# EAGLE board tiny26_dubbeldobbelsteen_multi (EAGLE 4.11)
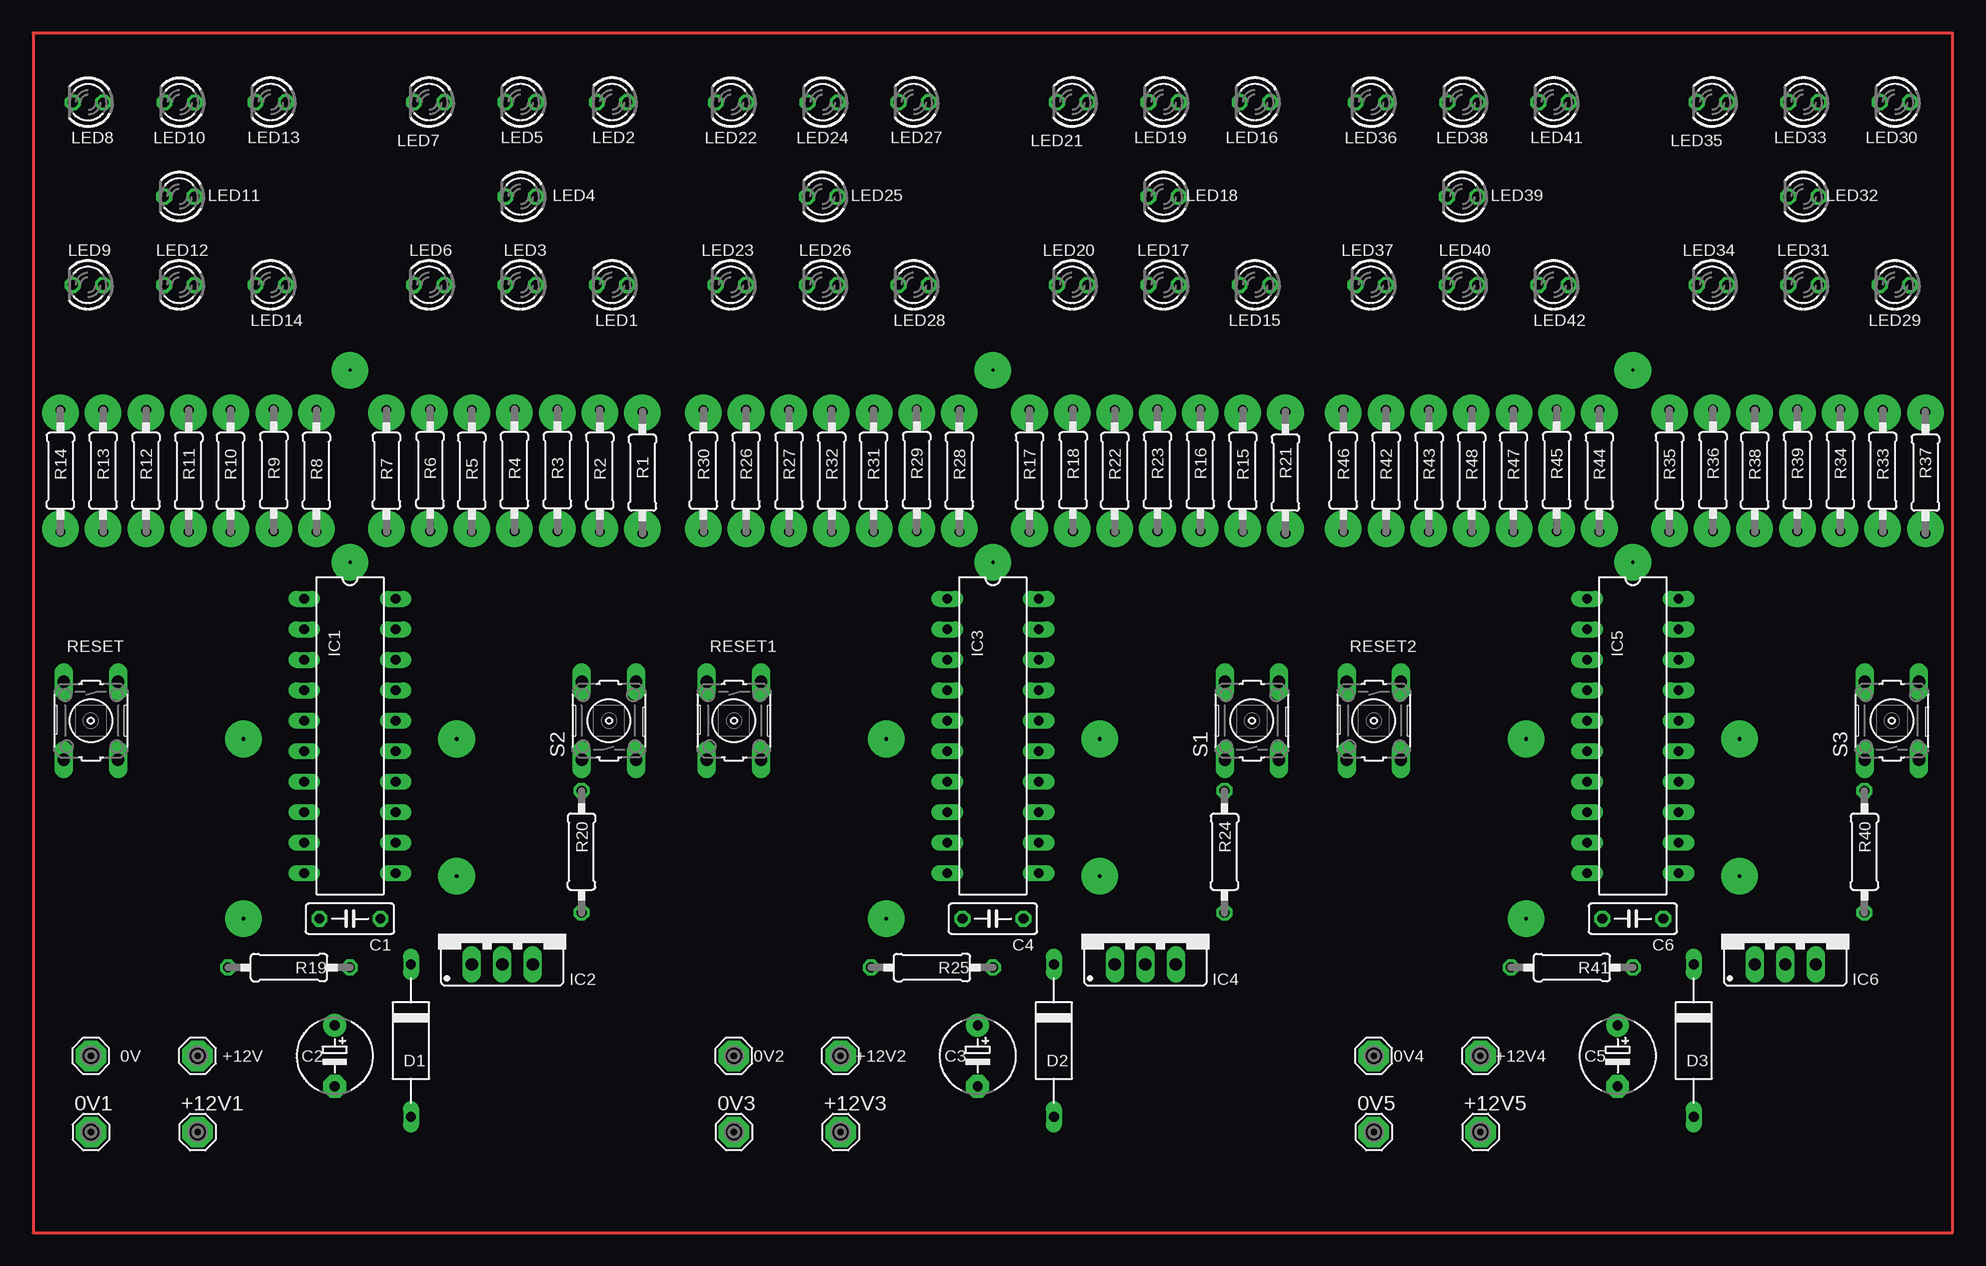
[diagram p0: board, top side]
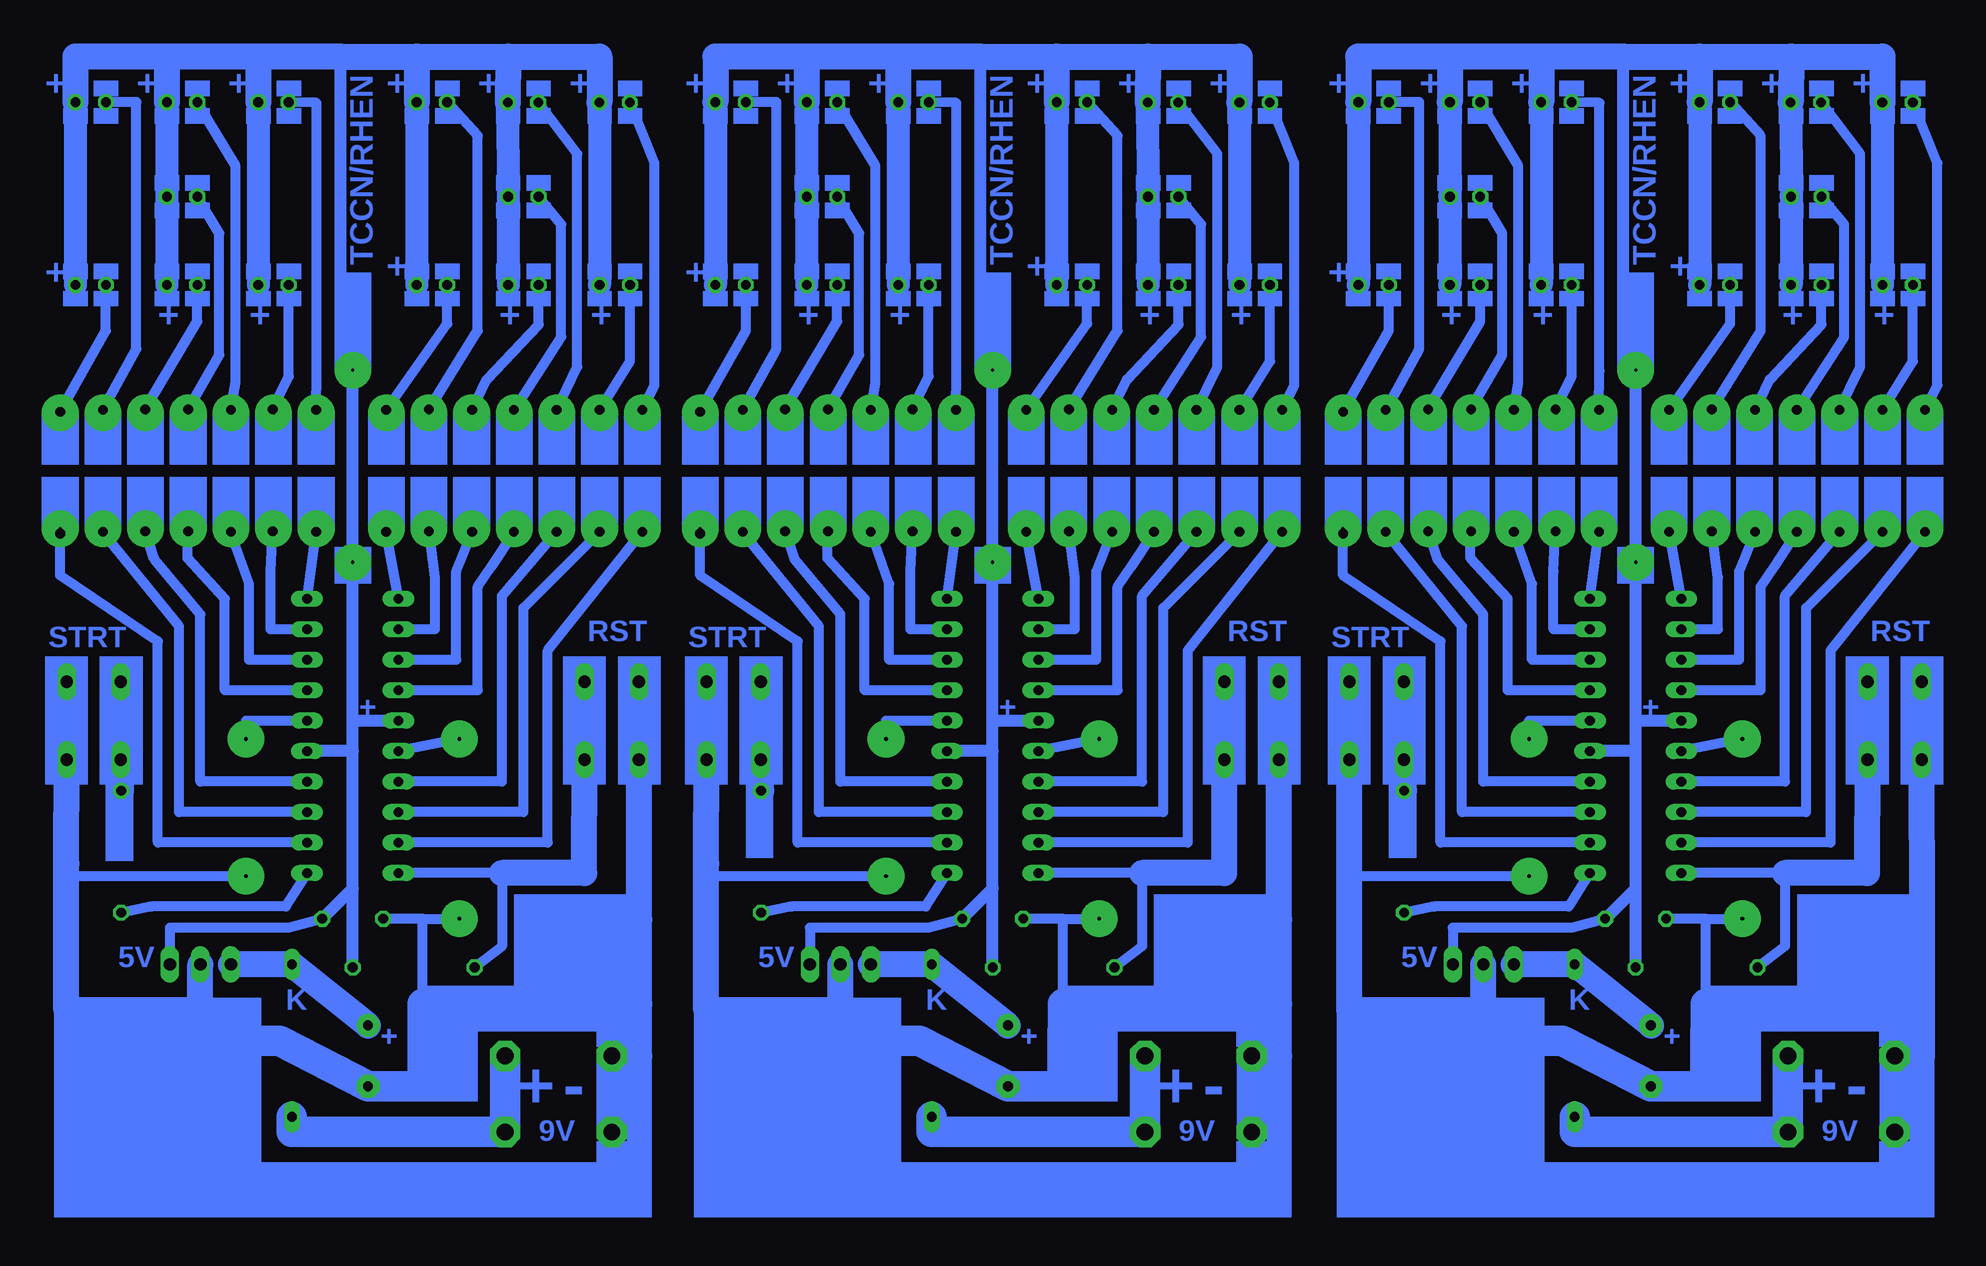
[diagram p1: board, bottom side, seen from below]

No outline drawn. Coordinates in mm, seen from the top.
Copper layers (1*16): Top 0.035mm / dielectric 1.5mm / Bottom 0.035mm
Design rules "default": minimum track width 15mil, minimum drill 24mil, track to track 15mil, track to pad 15mil, pad to pad 15mil, via to via 15mil, smd to smd 8mil, copper to edge 15mil, drill to drill 8mil, minimum pad ring 10mil, minimum via ring 8mil, stop-mask expansion 4mil, vias tented up to drill 0mil, thermal gap 10mil

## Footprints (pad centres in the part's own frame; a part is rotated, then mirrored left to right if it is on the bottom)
SE14 = drill 1.397 pad 2.54 octagon: MP 0,0
C050-025X075 = drill 0.813 octagon: 1 -2.54,0; 2 2.54,0
E5-6 = drill 0.813 pad 1.905 round: + -2.54,0 | drill 0.813 pad 1.905 octagon: - 2.54,0
D-12.5 = drill 0.813 long: A 6.35,0; C -6.35,0
DIL20 = drill 0.813 long: 1 -11.43,-3.81; 2 -8.89,-3.81; 3 -6.35,-3.81; 4 -3.81,-3.81; 5 -1.27,-3.81; 6 1.27,-3.81; 7 3.81,-3.81; 8 6.35,-3.81; 9 8.89,-3.81; 10 11.43,-3.81; 11 11.43,3.81; 12 8.89,3.81; 13 6.35,3.81; 14 3.81,3.81; 15 1.27,3.81; 16 -1.27,3.81; 17 -3.81,3.81; 18 -6.35,3.81; 19 -8.89,3.81; 20 -11.43,3.81
78XXS = drill 1.016 long: GND 0,-2.54; IN -2.54,-2.54; OUT 2.54,-2.54
LED3MM = drill 0.813 octagon: A -1.27,0; K 1.27,0
0207/10 = drill 0.813 octagon: 1 -5.08,0; 2 5.08,0
B3F-10XX = drill 1.016 long: 1 -3.251,2.261; 2 3.251,2.261; 3 -3.251,-2.261; 4 3.251,-2.261

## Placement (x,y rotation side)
0V  SE14  [SE14]  4.83,14.73 180 top
0V1  SE14  [SE14]  4.83,8.38 0 top
0V2  SE14  [SE14]  58.42,14.73 180 top
0V3  SE14  [SE14]  58.42,8.38 0 top
0V4  SE14  [SE14]  111.76,14.73 180 top
0V5  SE14  [SE14]  111.76,8.38 0 top
+12V  SE14  [SE14]  13.72,14.73 180 top
+12V1  SE14  [SE14]  13.72,8.38 0 top
+12V2  SE14  [SE14]  67.31,14.73 180 top
+12V3  SE14  [SE14]  67.31,8.38 0 top
+12V4  SE14  [SE14]  120.65,14.73 180 top
+12V5  SE14  [SE14]  120.65,8.38 0 top
C1  100nF  [C050-025X075]  26.42,26.16 180 top
C2  470uF  [E5-6]  25.15,14.73 270 top
C3  470uF  [E5-6]  78.74,14.73 270 top
C4  100nF  [C050-025X075]  80.01,26.16 180 top
C5  470uF  [E5-6]  132.08,14.73 270 top
C6  100nF  [C050-025X075]  133.35,26.16 180 top
D1  1N4003  [D-12.5]  31.5,16 270 top
D2  1N4003  [D-12.5]  85.09,16 270 top
D3  1N4003  [D-12.5]  138.43,16 270 top
IC1  ATtiny26  [DIL20]  26.42,41.4 270 top
IC2  7805  [78XXS]  39.12,24.89 0 top
IC3  ATtiny26  [DIL20]  80.01,41.4 270 top
IC4  7805  [78XXS]  92.71,24.89 0 top
IC5  ATtiny26  [DIL20]  133.35,41.4 270 top
IC6  7805  [78XXS]  146.05,24.89 0 top
LED1  [LED3MM]  48.26,78.99 180 top
LED2  [LED3MM]  48.26,94.23 180 top
LED3  [LED3MM]  40.64,78.99 180 top
LED4  [LED3MM]  40.64,86.36 180 top
LED5  [LED3MM]  40.64,94.23 180 top
LED6  [LED3MM]  33.02,78.99 180 top
LED7  [LED3MM]  33.02,94.23 180 top
LED8  [LED3MM]  4.59,94.22 180 top
LED9  [LED3MM]  4.57,78.99 180 top
LED10  [LED3MM]  12.22,94.22 180 top
LED11  [LED3MM]  12.19,86.36 180 top
LED12  [LED3MM]  12.19,78.99 180 top
LED13  [LED3MM]  19.81,94.23 180 top
LED14  [LED3MM]  19.81,78.99 180 top
LED15  [LED3MM]  101.85,78.99 180 top
LED16  [LED3MM]  101.85,94.23 180 top
LED17  [LED3MM]  94.23,78.99 180 top
LED18  [LED3MM]  94.23,86.36 180 top
LED19  [LED3MM]  94.23,94.23 180 top
LED20  [LED3MM]  86.61,78.99 180 top
LED21  [LED3MM]  86.61,94.23 180 top
LED22  [LED3MM]  58.18,94.22 180 top
LED23  [LED3MM]  58.17,78.99 180 top
LED24  [LED3MM]  65.82,94.22 180 top
LED25  [LED3MM]  65.79,86.36 180 top
LED26  [LED3MM]  65.79,78.99 180 top
LED27  [LED3MM]  73.41,94.23 180 top
LED28  [LED3MM]  73.41,78.99 180 top
LED29  [LED3MM]  155.19,78.99 180 top
LED30  [LED3MM]  155.19,94.23 180 top
LED31  [LED3MM]  147.57,78.99 180 top
LED32  [LED3MM]  147.57,86.36 180 top
LED33  [LED3MM]  147.57,94.23 180 top
LED34  [LED3MM]  139.95,78.99 180 top
LED35  [LED3MM]  139.95,94.23 180 top
LED36  [LED3MM]  111.52,94.22 180 top
LED37  [LED3MM]  111.51,78.99 180 top
LED38  [LED3MM]  119.16,94.22 180 top
LED39  [LED3MM]  119.13,86.36 180 top
LED40  [LED3MM]  119.13,78.99 180 top
LED41  [LED3MM]  126.75,94.23 180 top
LED42  [LED3MM]  126.75,78.99 180 top
R1  150  [0207/10]  50.8,63.35 90 top
R2  150  [0207/10]  47.24,63.5 90 top
R3  150  [0207/10]  43.71,63.55 90 top
R4  150  [0207/10]  40.13,63.55 90 top
R5  150  [0207/10]  36.58,63.5 90 top
R6  150  [0207/10]  33.1,63.55 90 top
R7  150  [0207/10]  29.46,63.5 90 top
R8  150  [0207/10]  23.62,63.5 90 top
R9  150  [0207/10]  20.07,63.55 90 top
R10  150  [0207/10]  16.46,63.5 90 top
R11  150  [0207/10]  12.98,63.5 90 top
R12  150  [0207/10]  9.42,63.5 90 top
R13  150  [0207/10]  5.84,63.5 90 top
R14  150  [0207/10]  2.29,63.5 90 top
R15  150  [0207/10]  100.84,63.5 90 top
R16  150  [0207/10]  97.31,63.55 90 top
R17  150  [0207/10]  83.06,63.5 90 top
R18  150  [0207/10]  86.69,63.55 90 top
R19  5K1  [0207/10]  21.34,22.1 0 top
R20  5K1  [0207/10]  45.72,31.75 270 top
R21  150  [0207/10]  104.39,63.35 90 top
R22  150  [0207/10]  90.17,63.5 90 top
R23  150  [0207/10]  93.73,63.55 90 top
R24  5K1  [0207/10]  99.31,31.75 270 top
R25  5K1  [0207/10]  74.93,22.1 0 top
R26  150  [0207/10]  59.44,63.5 90 top
R27  150  [0207/10]  63.02,63.5 90 top
R28  150  [0207/10]  77.22,63.5 90 top
R29  150  [0207/10]  73.66,63.55 90 top
R30  150  [0207/10]  55.88,63.5 90 top
R31  150  [0207/10]  70.05,63.5 90 top
R32  150  [0207/10]  66.57,63.5 90 top
R33  150  [0207/10]  154.18,63.5 90 top
R34  150  [0207/10]  150.65,63.55 90 top
R35  150  [0207/10]  136.4,63.5 90 top
R36  150  [0207/10]  140.03,63.55 90 top
R37  150  [0207/10]  157.73,63.35 90 top
R38  150  [0207/10]  143.51,63.5 90 top
R39  150  [0207/10]  147.07,63.55 90 top
R40  5K1  [0207/10]  152.65,31.75 270 top
R41  5K1  [0207/10]  128.27,22.1 0 top
R42  150  [0207/10]  112.78,63.5 90 top
R43  150  [0207/10]  116.36,63.5 90 top
R44  150  [0207/10]  130.56,63.5 90 top
R45  150  [0207/10]  127,63.55 90 top
R46  150  [0207/10]  109.22,63.5 90 top
R47  150  [0207/10]  123.39,63.5 90 top
R48  150  [0207/10]  119.91,63.5 90 top
RESET  [B3F-10XX]  4.83,42.67 270 top
RESET1  [B3F-10XX]  58.42,42.67 270 top
RESET2  [B3F-10XX]  111.76,42.67 270 top
S1  start  [B3F-10XX]  101.6,42.67 90 top
S2  start  [B3F-10XX]  48.01,42.67 90 top
S3  start  [B3F-10XX]  154.94,42.67 90 top

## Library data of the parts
0V 0V1-0V5 +12V +12V1-+12V5 = solpad
C1-C6 R1-R48 = rcl
D1-D3 = diode
IC1 IC3 IC5 = atmel
IC2 IC4 IC6 = v-reg
LED1-LED42 = led
RESET RESET1 RESET2 S1-S3 = switch-omron

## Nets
+12V: +12V1.MP +12V.MP D1.A
+12V1: +12V2.MP +12V3.MP D2.A
+12V2: +12V4.MP +12V5.MP D3.A
B0_MOSI: IC1.1 R8.1
B0_MOSI1: IC3.1 R28.1
B0_MOSI2: IC5.1 R44.1
B1: IC3.4 R32.1
B1_MISO: IC1.2 R9.1
B1_MISO1: IC3.2 R29.1
B1_MISO2: IC5.2 R45.1
B2: IC3.7 R27.1
B2_SCK: IC1.3 R10.1
B2_SCK1: IC3.3 R31.1
B2_SCK2: IC5.3 R47.1
B3: IC1.4 R11.1
B4: IC1.7 R12.1
B5: IC5.4 R48.1
B6: IC5.7 R43.1
GND: 0V1.MP 0V.MP C1.2 C2.- IC1.6 IC1.16 IC2.GND RESET.4 S2.3
GND1: 0V2.MP 0V3.MP C3.- C4.2 IC3.6 IC3.16 IC4.GND RESET1.4 S1.3
GND2: 0V4.MP 0V5.MP C5.- C6.2 IC5.6 IC5.16 IC6.GND RESET2.4 S3.3
N$1: C3.+ D2.C IC4.IN
N$3: R20.1 S2.1
N$4: R24.1 S1.1
N$5: LED7.K R7.2
N$6: LED6.K R6.2
N$7: LED5.K R5.2
N$8: LED4.K R4.2
N$9: LED3.K R3.2
N$10: C2.+ D1.C IC2.IN
N$11: LED2.K R2.2
N$12: LED1.K R1.2
N$13: LED21.K R17.2
N$14: IC1.20 R7.1
N$15: IC1.19 R6.1
N$16: LED20.K R18.2
N$17: IC1.18 R5.1
N$18: IC1.17 R4.1
N$19: IC1.14 R3.1
N$20: IC1.13 R2.1
N$21: IC1.12 R1.1
N$23: LED14.K R8.2
N$24: LED13.K R9.2
N$25: LED12.K R10.2
N$26: LED11.K R11.2
N$27: LED10.K R12.2
N$28: LED9.K R13.2
N$29: LED8.K R14.2
N$30: IC1.8 R13.1
N$31: IC1.9 R14.1
N$60: LED19.K R22.2
N$61: LED18.K R23.2
N$62: IC1.11 R20.2
N$63: LED17.K R16.2
N$64: LED16.K R15.2
N$65: LED15.K R21.2
N$66: IC3.20 R17.1
N$67: IC3.19 R18.1
N$68: IC3.18 R22.1
N$69: IC3.17 R23.1
N$70: IC3.14 R16.1
N$71: IC3.13 R15.1
N$72: IC3.12 R21.1
N$73: LED28.K R28.2
N$74: LED27.K R29.2
N$75: LED26.K R31.2
N$76: LED25.K R32.2
N$77: LED24.K R27.2
N$78: LED23.K R26.2
N$79: LED22.K R30.2
N$80: IC3.8 R26.1
N$81: IC3.9 R30.1
N$112: IC3.11 R24.2
N$113: C5.+ D3.C IC6.IN
N$114: R40.1 S3.1
N$115: LED35.K R35.2
N$116: LED34.K R36.2
N$117: LED33.K R38.2
N$118: LED32.K R39.2
N$119: LED31.K R34.2
N$120: LED30.K R33.2
N$121: LED29.K R37.2
N$122: IC5.20 R35.1
N$123: IC5.19 R36.1
N$124: IC5.18 R38.1
N$125: IC5.17 R39.1
N$126: IC5.14 R34.1
N$127: IC5.13 R33.1
N$128: IC5.12 R37.1
N$129: LED42.K R44.2
N$130: LED41.K R45.2
N$131: LED40.K R47.2
N$132: LED39.K R48.2
N$133: LED38.K R43.2
N$134: LED37.K R42.2
N$135: LED36.K R46.2
N$136: IC5.8 R42.1
N$137: IC5.9 R46.1
N$168: IC5.11 R40.2
RESET: IC1.10 R19.1 RESET.2
RESET1: IC3.10 R25.1 RESET1.2
RESET2: IC5.10 R41.1 RESET2.2
VCC: C1.1 IC1.5 IC1.15 IC2.OUT LED1.A LED2.A LED3.A LED4.A LED5.A LED6.A LED7.A LED8.A LED9.A LED10.A LED11.A LED12.A LED13.A LED14.A R19.2
VCC1: C4.1 IC3.5 IC3.15 IC4.OUT LED15.A LED16.A LED17.A LED18.A LED19.A LED20.A LED21.A LED22.A LED23.A LED24.A LED25.A LED26.A LED27.A LED28.A R25.2
VCC2: C6.1 IC5.5 IC5.15 IC6.OUT LED29.A LED30.A LED31.A LED32.A LED33.A LED34.A LED35.A LED36.A LED37.A LED38.A LED39.A LED40.A LED41.A LED42.A R41.2

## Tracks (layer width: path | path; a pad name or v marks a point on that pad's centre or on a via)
+12V
  Bottom 2.54: +12V.MP +12V1.MP 31.5,8.38 D1.A
+12V1
  Bottom 2.54: +12V2.MP +12V3.MP 85.09,8.38 D2.A
+12V2
  Bottom 2.54: +12V4.MP +12V5.MP 138.43,8.38 D3.A
B0_MOSI
  Bottom 0.813: IC1.1 R8.1
B0_MOSI1
  Bottom 0.813: IC3.1 R28.1
B0_MOSI2
  Bottom 0.813: IC5.1 R44.1
B1
  Bottom 0.813: IC3.4 69.6,45.21 69.6,53.85 68.43,55.55 R32.1
B1_MISO
  Bottom 0.813: IC1.2 19.56,50.29 19.56,54.61 R9.1
B1_MISO1
  Bottom 0.813: IC3.2 73.15,50.29 73.15,54.61 R29.1
B1_MISO2
  Bottom 0.813: IC5.2 126.49,50.29 126.49,54.61 R45.1
B2
  Bottom 0.813: IC3.7 67.56,37.59 67.56,53.09 R27.1
B2_SCK
  Bottom 0.813: IC1.3 17.78,47.75 17.78,55.12 R10.1
B2_SCK1
  Bottom 0.813: IC3.3 71.37,47.75 71.37,55.12 R31.1
B2_SCK2
  Bottom 0.813: IC5.3 124.71,47.75 124.71,55.12 R47.1
B3
  Bottom 0.813: IC1.4 16,45.21 16,53.85 14.83,55.55 R11.1
B4
  Bottom 0.813: IC1.7 13.97,37.59 13.97,53.09 R12.1
B5
  Bottom 0.813: IC5.4 122.94,45.21 122.94,53.85 121.77,55.55 R48.1
B6
  Bottom 0.813: IC5.7 120.9,37.59 120.9,53.09 R43.1
GND  (via drill 0.3 pad 3.05)
  Bottom 0.406: 2.54,19.05 20.57,19.05
  Bottom 0.813: v35.31,41.15 35.31,42.67 IC1.16 | v17.53,41.15 IC1.6 | 50.29,29.72 v35.31,29.72 | 20.57,26.16 v17.53,26.16 | 20.57,19.05 20.57,26.16 | 20.57,26.16 C1.2 | 35.31,16 35.31,18.54 39.12,18.54
  Bottom 1.422: 50.29,30.73 50.55,30.73
  Bottom 2.184: S2.3 50.29,30.73 50.29,29.72 50.29,18.54 39.12,18.54 IC2.GND | RESET.4 2.54,26.09 2.54,19.05 2.54,14.73 0V.MP
  Bottom 2.54: 35.31,16 32.51,16 C2.- 20.57,12.19 20.57,19.05 | 0V1.MP 0V.MP
GND1  (via drill 0.3 pad 3.05)
  Bottom 0.406: 56.13,19.05 74.17,19.05
  Bottom 0.813: v88.9,41.15 88.9,42.67 IC3.16 | v71.12,41.15 IC3.6 | 103.89,29.72 v88.9,29.72 | 74.17,26.16 v71.12,26.16 | 74.17,19.05 74.17,26.16 | 74.17,26.16 C4.2 | 88.9,16 88.9,18.54 92.71,18.54
  Bottom 1.422: 103.88,30.73 104.14,30.73
  Bottom 2.184: S1.3 103.88,30.73 103.89,29.72 103.89,18.54 92.71,18.54 IC4.GND | RESET1.4 56.13,26.09 56.13,19.05 56.13,14.73 0V2.MP
  Bottom 2.54: 88.9,16 86.11,16 C3.- 74.17,12.19 74.17,19.05 | 0V3.MP 0V2.MP
GND2  (via drill 0.3 pad 3.05)
  Bottom 0.406: 109.47,19.05 127.51,19.05
  Bottom 0.813: v142.24,41.15 142.24,42.67 IC5.16 | v124.46,41.15 IC5.6 | 157.23,29.72 v142.24,29.72 | 127.51,26.16 v124.46,26.16 | 127.51,19.05 127.51,26.16 | 127.51,26.16 C6.2 | 142.24,16 142.24,18.54 146.05,18.54
  Bottom 1.422: 157.22,30.73 157.48,30.73
  Bottom 2.184: S3.3 157.22,30.73 157.23,29.72 157.23,18.54 146.05,18.54 IC6.GND | RESET2.4 109.47,26.09 109.47,19.05 109.47,14.73 0V4.MP
  Bottom 2.54: 142.24,16 139.45,16 C5.- 127.51,12.19 127.51,19.05 | 0V5.MP 0V4.MP
N$1
  Bottom 2.184: C3.+ D2.C IC4.IN
N$2  (via drill 0.25 pad 3.05)
  other vias: 2.29,68.33
N$3
  Bottom 0.813: 45.72,39.37 S2.1
  Bottom 2.184: R20.1 45.72,39.37
N$4
  Bottom 0.813: 99.31,39.37 S1.1
  Bottom 2.184: R24.1 99.31,39.37
N$5
  Bottom 0.813: LED7.K 29.44,94.18 29.44,71.83 R7.2
N$6
  Bottom 0.813: R6.2 31.75,71.37 LED6.K
N$7
  Bottom 0.813: LED5.K 36.2,88.92 36.2,70.87 R5.2
N$8
  Bottom 0.813: LED4.K 37.54,83.31 37.54,73.15 R4.2
N$9
  Bottom 0.813: LED3.K 39.37,75.95 R3.2
N$10
  Bottom 2.184: C2.+ D1.C IC2.IN
N$11
  Bottom 0.813: LED2.K 44.45,94.23 44.45,73.66 R2.2
N$12
  Bottom 0.813: R1.2 46.99,75.18 LED1.K
N$13
  Bottom 0.813: LED21.K 83.03,94.18 83.03,71.83 R17.2
N$14
  Bottom 0.813: IC1.20 R7.1
N$15
  Bottom 0.813: IC1.19 33.27,50.29 33.27,55.12 R6.1
N$16
  Bottom 0.813: R18.2 85.34,71.37 LED20.K
N$17
  Bottom 0.813: IC1.18 35.05,47.75 35.05,54.1 R5.1
N$18
  Bottom 0.813: IC1.17 37.08,45.21 37.08,52.83 40.18,56.21 R4.1
N$19
  Bottom 0.813: IC1.14 39.12,37.59 39.12,51.56 42.95,56.16 R3.1
N$20
  Bottom 0.813: IC1.13 40.89,35.05 40.89,50.55 R2.1
N$21
  Bottom 0.813: IC1.12 42.67,32.51 42.67,49.28 50.8,54.79 R1.1
N$22  (via drill 0.25 pad 3.05)
  other vias: 5.84,68.33
N$23
  Bottom 0.813: LED14.K 18.54,75.77 R8.2
N$24
  Bottom 0.813: LED13.K 16,91.44 16,75.18 R9.2
N$25
  Bottom 0.813: R10.2 15.24,71.12 10.92,75.69 LED12.K
N$26
  Bottom 0.813: R11.2 9.04,74.65 9.04,84.05 LED11.K
N$27
  Bottom 0.813: LED10.K 7.7,89.94 7.7,72.16 R12.2
N$28
  Bottom 0.813: LED9.K 3.3,72.64 R13.2
N$29
  Bottom 0.813: LED8.K 1.27,89.15 1.27,70.61 R14.2
N$30
  Bottom 0.813: IC1.8 12.19,35.05 12.19,52.07 R13.1
N$31
  Bottom 0.813: IC1.9 10.16,32.51 10.16,48.51 R14.1
N$32  (via drill 0.25 pad 3.05)
  other vias: 9.4,68.33
N$33  (via drill 0.25 pad 3.05)
  other vias: 12.95,68.33
N$34  (via drill 0.25 pad 3.05)
  other vias: 2.29,58.67
N$35  (via drill 0.25 pad 3.05)
  other vias: 5.84,58.67
N$36  (via drill 0.25 pad 3.05)
  other vias: 9.4,58.67
N$37  (via drill 0.25 pad 3.05)
  other vias: 12.95,58.67
N$38  (via drill 0.25 pad 3.05)
  other vias: 16.51,68.33
N$39  (via drill 0.25 pad 3.05)
  other vias: 20.07,68.33
N$40  (via drill 0.25 pad 3.05)
  other vias: 23.62,68.33
N$41  (via drill 0.25 pad 3.05)
  other vias: 29.46,68.33
N$42  (via drill 0.25 pad 3.05)
  other vias: 33.02,68.33
N$43  (via drill 0.25 pad 3.05)
  other vias: 29.46,58.67
N$44  (via drill 0.25 pad 3.05)
  other vias: 23.62,58.67
N$45  (via drill 0.25 pad 3.05)
  other vias: 20.07,58.67
N$46  (via drill 0.25 pad 3.05)
  other vias: 16.51,58.67
N$47  (via drill 0.25 pad 3.05)
  other vias: 33.02,58.67
N$48  (via drill 0.25 pad 3.05)
  other vias: 36.58,68.33
N$49  (via drill 0.25 pad 3.05)
  other vias: 36.58,58.67
N$50  (via drill 0.25 pad 3.05)
  other vias: 40.13,68.33
N$51  (via drill 0.25 pad 3.05)
  other vias: 40.13,58.67
N$52  (via drill 0.25 pad 3.05)
  other vias: 43.69,68.33
N$53  (via drill 0.25 pad 3.05)
  other vias: 43.69,58.67
N$54  (via drill 0.25 pad 3.05)
  other vias: 47.24,68.33
N$55  (via drill 0.25 pad 3.05)
  other vias: 47.24,58.67
N$56  (via drill 0.25 pad 3.05)
  other vias: 50.8,68.33
N$57  (via drill 0.25 pad 3.05)
  other vias: 50.8,58.67
N$58  (via drill 0.25 pad 3.05)
  other vias: 26.42,71.88
N$59  (via drill 0.25 pad 3.05)
  other vias: 26.42,55.88
N$60
  Bottom 0.813: LED19.K 89.79,88.92 89.79,70.87 R22.2
N$61
  Bottom 0.813: LED18.K 91.14,83.31 91.14,73.15 R23.2
N$62
  Bottom 0.813: IC1.11 32,27.18 43.18,27.18 R20.2
N$63
  Bottom 0.813: LED17.K 92.96,75.95 R16.2
N$64
  Bottom 0.813: LED16.K 98.04,94.23 98.04,73.66 R15.2
N$65
  Bottom 0.813: R21.2 100.58,75.18 LED15.K
N$66
  Bottom 0.813: IC3.20 R17.1
N$67
  Bottom 0.813: IC3.19 86.87,50.29 86.87,55.12 R18.1
N$68
  Bottom 0.813: IC3.18 88.65,47.75 88.65,54.1 R22.1
N$69
  Bottom 0.813: IC3.17 90.68,45.21 90.68,52.83 93.78,56.21 R23.1
N$70
  Bottom 0.813: IC3.14 92.71,37.59 92.71,51.56 96.55,56.16 R16.1
N$71
  Bottom 0.813: IC3.13 94.49,35.05 94.49,50.55 R15.1
N$72
  Bottom 0.813: IC3.12 96.27,32.51 96.27,49.28 104.39,54.79 R21.1
N$73
  Bottom 0.813: LED28.K 72.14,75.77 R28.2
N$74
  Bottom 0.813: LED27.K 69.6,91.44 69.6,75.18 R29.2
N$75
  Bottom 0.813: R31.2 68.83,71.12 64.52,75.69 LED26.K
N$76
  Bottom 0.813: R32.2 62.64,74.65 62.64,84.05 LED25.K
N$77
  Bottom 0.813: LED24.K 61.29,89.94 61.29,72.16 R27.2
N$78
  Bottom 0.813: LED23.K 56.9,72.64 R26.2
N$79
  Bottom 0.813: LED22.K 54.86,89.15 54.86,70.61 R30.2
N$80
  Bottom 0.813: IC3.8 65.79,35.05 65.79,52.07 R26.1
N$81
  Bottom 0.813: IC3.9 63.75,32.51 63.75,48.51 R30.1
N$82  (via drill 0.25 pad 3.05)
  other vias: 55.88,68.33
N$83  (via drill 0.25 pad 3.05)
  other vias: 59.44,68.33
N$84  (via drill 0.25 pad 3.05)
  other vias: 62.99,68.33
N$85  (via drill 0.25 pad 3.05)
  other vias: 66.55,68.33
N$86  (via drill 0.25 pad 3.05)
  other vias: 55.88,58.67
N$87  (via drill 0.25 pad 3.05)
  other vias: 59.44,58.67
N$88  (via drill 0.25 pad 3.05)
  other vias: 62.99,58.67
N$89  (via drill 0.25 pad 3.05)
  other vias: 66.55,58.67
N$90  (via drill 0.25 pad 3.05)
  other vias: 70.1,68.33
N$91  (via drill 0.25 pad 3.05)
  other vias: 73.66,68.33
N$92  (via drill 0.25 pad 3.05)
  other vias: 77.22,68.33
N$93  (via drill 0.25 pad 3.05)
  other vias: 83.06,68.33
N$94  (via drill 0.25 pad 3.05)
  other vias: 86.61,68.33
N$95  (via drill 0.25 pad 3.05)
  other vias: 83.06,58.67
N$96  (via drill 0.25 pad 3.05)
  other vias: 77.22,58.67
N$97  (via drill 0.25 pad 3.05)
  other vias: 73.66,58.67
N$98  (via drill 0.25 pad 3.05)
  other vias: 70.1,58.67
N$99  (via drill 0.25 pad 3.05)
  other vias: 86.61,58.67
N$100  (via drill 0.25 pad 3.05)
  other vias: 90.17,68.33
N$101  (via drill 0.25 pad 3.05)
  other vias: 90.17,58.67
N$102  (via drill 0.25 pad 3.05)
  other vias: 93.73,68.33
N$103  (via drill 0.25 pad 3.05)
  other vias: 93.73,58.67
N$104  (via drill 0.25 pad 3.05)
  other vias: 97.28,68.33
N$105  (via drill 0.25 pad 3.05)
  other vias: 97.28,58.67
N$106  (via drill 0.25 pad 3.05)
  other vias: 100.84,68.33
N$107  (via drill 0.25 pad 3.05)
  other vias: 100.84,58.67
N$108  (via drill 0.25 pad 3.05)
  other vias: 104.39,68.33
N$109  (via drill 0.25 pad 3.05)
  other vias: 104.39,58.67
N$110  (via drill 0.25 pad 3.05)
  other vias: 80.01,71.88
N$111  (via drill 0.25 pad 3.05)
  other vias: 80.01,55.88
N$112
  Bottom 0.813: IC3.11 85.6,27.18 96.77,27.18 R24.2
N$113
  Bottom 2.184: C5.+ D3.C IC6.IN
N$114
  Bottom 0.813: 152.65,39.37 S3.1
  Bottom 2.184: R40.1 152.65,39.37
N$115
  Bottom 0.813: LED35.K 136.37,94.18 136.37,71.83 R35.2
N$116
  Bottom 0.813: R36.2 138.68,71.37 LED34.K
N$117
  Bottom 0.813: LED33.K 143.13,88.92 143.13,70.87 R38.2
N$118
  Bottom 0.813: LED32.K 144.47,83.31 144.47,73.15 R39.2
N$119
  Bottom 0.813: LED31.K 146.3,75.95 R34.2
N$120
  Bottom 0.813: LED30.K 151.38,94.23 151.38,73.66 R33.2
N$121
  Bottom 0.813: R37.2 153.92,75.18 LED29.K
N$122
  Bottom 0.813: IC5.20 R35.1
N$123
  Bottom 0.813: IC5.19 140.21,50.29 140.21,55.12 R36.1
N$124
  Bottom 0.813: IC5.18 141.99,47.75 141.99,54.1 R38.1
N$125
  Bottom 0.813: IC5.17 144.02,45.21 144.02,52.83 147.12,56.21 R39.1
N$126
  Bottom 0.813: IC5.14 146.05,37.59 146.05,51.56 149.88,56.16 R34.1
N$127
  Bottom 0.813: IC5.13 147.83,35.05 147.83,50.55 R33.1
N$128
  Bottom 0.813: IC5.12 149.61,32.51 149.61,49.28 157.73,54.79 R37.1
N$129
  Bottom 0.813: LED42.K 125.48,75.77 R44.2
N$130
  Bottom 0.813: LED41.K 122.94,91.44 122.94,75.18 R45.2
N$131
  Bottom 0.813: R47.2 122.17,71.12 117.86,75.69 LED40.K
N$132
  Bottom 0.813: R48.2 115.98,74.65 115.98,84.05 LED39.K
N$133
  Bottom 0.813: LED38.K 114.63,89.94 114.63,72.16 R43.2
N$134
  Bottom 0.813: LED37.K 110.24,72.64 R42.2
N$135
  Bottom 0.813: LED36.K 108.2,89.15 108.2,70.61 R46.2
N$136
  Bottom 0.813: IC5.8 119.13,35.05 119.13,52.07 R42.1
N$137
  Bottom 0.813: IC5.9 117.09,32.51 117.09,48.51 R46.1
N$138  (via drill 0.25 pad 3.05)
  other vias: 109.22,68.33
N$139  (via drill 0.25 pad 3.05)
  other vias: 112.78,68.33
N$140  (via drill 0.25 pad 3.05)
  other vias: 116.33,68.33
N$141  (via drill 0.25 pad 3.05)
  other vias: 119.89,68.33
N$142  (via drill 0.25 pad 3.05)
  other vias: 109.22,58.67
N$143  (via drill 0.25 pad 3.05)
  other vias: 112.78,58.67
N$144  (via drill 0.25 pad 3.05)
  other vias: 116.33,58.67
N$145  (via drill 0.25 pad 3.05)
  other vias: 119.89,58.67
N$146  (via drill 0.25 pad 3.05)
  other vias: 123.44,68.33
N$147  (via drill 0.25 pad 3.05)
  other vias: 127,68.33
N$148  (via drill 0.25 pad 3.05)
  other vias: 130.56,68.33
N$149  (via drill 0.25 pad 3.05)
  other vias: 136.4,68.33
N$150  (via drill 0.25 pad 3.05)
  other vias: 139.95,68.33
N$151  (via drill 0.25 pad 3.05)
  other vias: 136.4,58.67
N$152  (via drill 0.25 pad 3.05)
  other vias: 130.56,58.67
N$153  (via drill 0.25 pad 3.05)
  other vias: 127,58.67
N$154  (via drill 0.25 pad 3.05)
  other vias: 123.44,58.67
N$155  (via drill 0.25 pad 3.05)
  other vias: 139.95,58.67
N$156  (via drill 0.25 pad 3.05)
  other vias: 143.51,68.33
N$157  (via drill 0.25 pad 3.05)
  other vias: 143.51,58.67
N$158  (via drill 0.25 pad 3.05)
  other vias: 147.07,68.33
N$159  (via drill 0.25 pad 3.05)
  other vias: 147.07,58.67
N$160  (via drill 0.25 pad 3.05)
  other vias: 150.62,68.33
N$161  (via drill 0.25 pad 3.05)
  other vias: 150.62,58.67
N$162  (via drill 0.25 pad 3.05)
  other vias: 154.18,68.33
N$163  (via drill 0.25 pad 3.05)
  other vias: 154.18,58.67
N$164  (via drill 0.25 pad 3.05)
  other vias: 157.73,68.33
N$165  (via drill 0.25 pad 3.05)
  other vias: 157.73,58.67
N$166  (via drill 0.25 pad 3.05)
  other vias: 133.35,71.88
N$167  (via drill 0.25 pad 3.05)
  other vias: 133.35,55.88
N$168
  Bottom 0.813: IC5.11 138.94,27.18 150.11,27.18 R40.2
RESET
  Bottom 0.813: IC1.10 13.97,29.97 13.97,23.88 R19.1
  Bottom 2.184: RESET.2 7.11,29.97 13.97,29.97
RESET1
  Bottom 0.813: IC3.10 67.56,29.97 67.56,23.88 R25.1
  Bottom 2.184: RESET1.2 60.71,29.97 67.56,29.97
RESET2
  Bottom 0.813: IC5.10 120.9,29.97 120.9,23.88 R41.1
  Bottom 2.184: RESET2.2 114.05,29.97 120.9,29.97
S$1
  Top 0.254: 0,0 160,0 160,100 0,100 0,0
VCC
  Bottom 0.813: IC2.OUT 41.66,25.4 31.75,25.4 C1.1
  Bottom 1.016: 26.42,42.67 IC1.5 | 26.42,42.67 26.42,75.95 27.43,75.95 27.43,98.04 | 26.42,28.7 26.42,40.13 | 26.42,40.13 26.42,42.67 | 26.42,28.7 C1.1 | 26.42,40.13 IC1.15 | R19.2 26.42,28.7 | LED8.A 5.84,94.23
  Bottom 1.93: LED2.A LED1.A | LED13.A LED14.A | LED7.A LED6.A | LED3.A LED4.A LED5.A | LED12.A LED11.A LED10.A | 5.84,94.23 LED9.A
  Bottom 2.184: 13.46,98.04 5.84,98.04 LED8.A | 21.08,98.04 LED13.A | 21.08,98.04 13.46,98.04 | 21.08,98.04 27.43,98.04 34.29,98.04 | 34.29,98.04 41.91,98.04 | LED2.A 49.53,98.04 41.91,98.04 | 34.29,98.04 LED7.A | 41.91,98.04 LED5.A | 13.46,98.04 LED10.A
VCC1
  Bottom 0.813: IC4.OUT 95.25,25.4 85.34,25.4 C4.1
  Bottom 1.016: 80.01,42.67 IC3.5 | 80.01,42.67 80.01,75.95 81.03,75.95 81.03,98.04 | 80.01,28.7 80.01,40.13 | 80.01,40.13 80.01,42.67 | 80.01,28.7 C4.1 | 80.01,40.13 IC3.15 | R25.2 80.01,28.7 | LED22.A 59.44,94.23
  Bottom 1.93: LED16.A LED15.A | LED27.A LED28.A | LED21.A LED20.A | LED17.A LED18.A LED19.A | LED26.A LED25.A LED24.A | 59.44,94.23 LED23.A
  Bottom 2.184: 67.06,98.04 59.44,98.04 LED22.A | 74.68,98.04 LED27.A | 74.68,98.04 67.06,98.04 | 74.68,98.04 81.03,98.04 87.88,98.04 | 87.88,98.04 95.5,98.04 | LED16.A 103.12,98.04 95.5,98.04 | 87.88,98.04 LED21.A | 95.5,98.04 LED19.A | 67.06,98.04 LED24.A
VCC2
  Bottom 0.813: IC6.OUT 148.59,25.4 138.68,25.4 C6.1
  Bottom 1.016: 133.35,42.67 IC5.5 | 133.35,42.67 133.35,75.95 134.37,75.95 134.37,98.04 | 133.35,28.7 133.35,40.13 | 133.35,40.13 133.35,42.67 | 133.35,28.7 C6.1 | 133.35,40.13 IC5.15 | R41.2 133.35,28.7 | LED36.A 112.78,94.23
  Bottom 1.93: LED30.A LED29.A | LED41.A LED42.A | LED35.A LED34.A | LED31.A LED32.A LED33.A | LED40.A LED39.A LED38.A | 112.78,94.23 LED37.A
  Bottom 2.184: 120.4,98.04 112.78,98.04 LED36.A | 128.02,98.04 LED41.A | 128.02,98.04 120.4,98.04 | 128.02,98.04 134.37,98.04 141.22,98.04 | 141.22,98.04 148.84,98.04 | LED30.A 156.46,98.04 148.84,98.04 | 141.22,98.04 LED35.A | 148.84,98.04 LED33.A | 120.4,98.04 LED38.A
(copper drawn outside any net)
  shapes: Bottom area x306

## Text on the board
Bottom: TCCN/RHEN | TCCN/RHEN | TCCN/RHEN | + | + | + | + | + | + | + | + | + | + | + | + | + | + | + | + | + | + | + | + | + | + | + | + | + | + | + | + | + | + | + | + | + | + | + | + | RST | STRT | RST | STRT | RST | STRT | + | + | + | 5V | 5V | 5V | K | K | K | + | + | + | - | + | - | + | - | + | 9V | 9V | 9V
